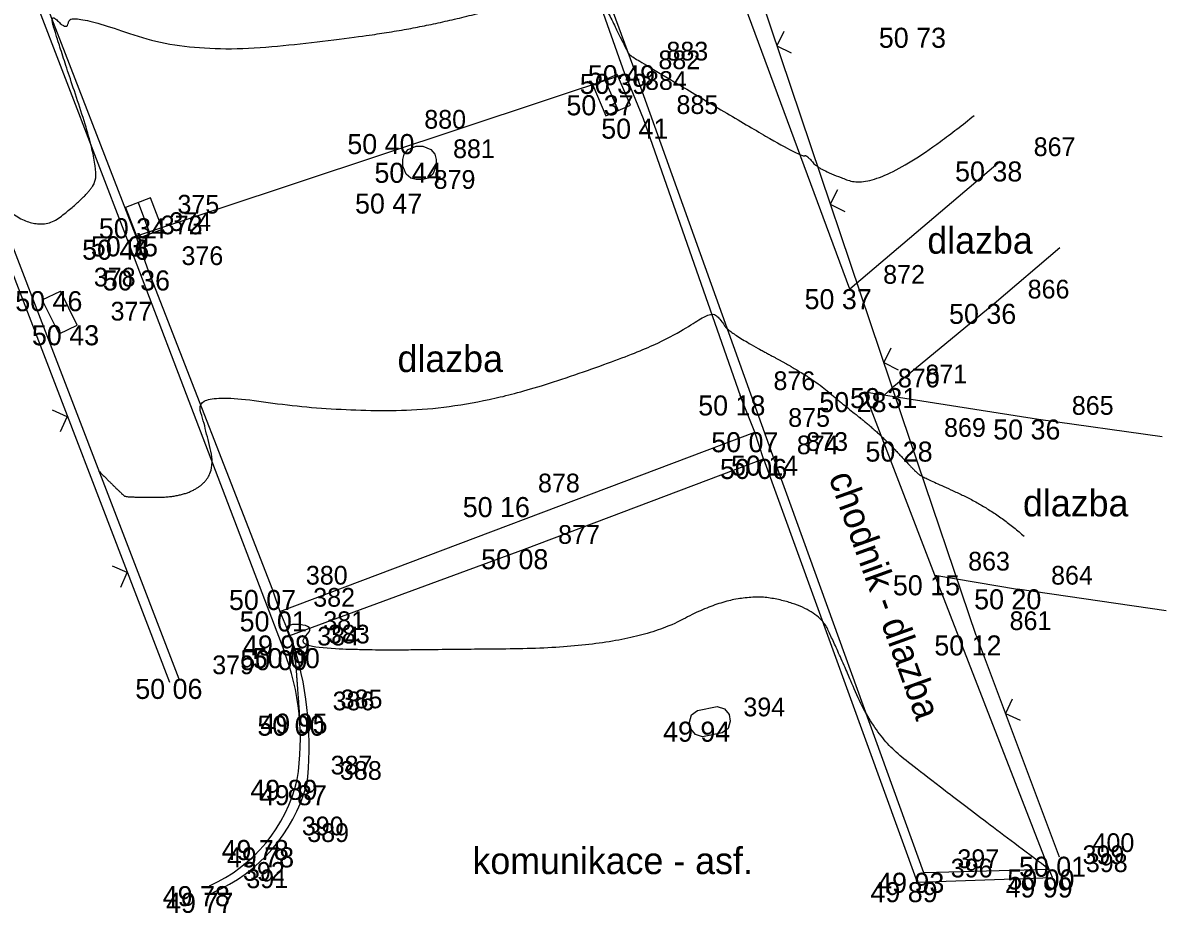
# Model space of a CAD drawing. Extents: x -704017 to -701500, y -1008977 to -1008450.
# Drawn here: x -703990.87 to -703973.78, y -1008677.56 to -1008664.25 of the extents above; entities that cross this region are included whole.
import ezdxf

# ---------------------------------------------------------------- set-up
doc = ezdxf.new("R2010")
doc.units = 0
for name, color, linetype in [('Z_body', 7, 'Continuous'), ('Z_body_cisla', 7, 'Continuous'), ('Z_body_vysky', 7, 'Continuous'), ('Z_chodnik', 7, 'Continuous'), ('Z_komunikace', 7, 'Continuous'), ('Z_obruby', 7, 'Continuous'), ('Z_popis', 7, 'Continuous'), ('Z_rozhrani_ploch', 7, 'Continuous'), ('Z_site_znaky_kanalizace', 7, 'Continuous'), ('Z_site_znaky_pilire', 7, 'Continuous'), ('Z_site_znaky_plynovod', 7, 'Continuous'), ('Z_teren_hrany_paty', 7, 'Continuous'), ('Z_vrstevnice_hlavni', 7, 'Continuous'), ('Z_vrstevnice_vedlejsi', 7, 'Continuous'), ('Z_vstupy', 7, 'Continuous')]:
    doc.layers.add(name, color=color, linetype=linetype)

# ---------------------------------------------------------------- blocks, each defined once
blk = doc.blocks.new('POINT_DISPLAY')
blk.add_line((0, 0), (0, 0))
blk = doc.blocks.new('Z212')
for p, q in [((-0.17, 0.17), (0, 0)), ((0, 0), (0.17, 0.17))]:
    blk.add_line(p, q)
blk = doc.blocks.new('Z620')
for p, q in [((-0.23, 0.13), (-0.17, 0.2)), ((-0.17, 0.2), (-0.05, 0.25)), ((-0.05, 0.25), (0.05, 0.25)), ((0.05, 0.25), (0.17, 0.2)), ((0.17, 0.2), (0.23, 0.13)), ((-0.25, 0.05), (-0.23, 0.13)), ((-0.25, -0.05), (-0.25, 0.05)), ((0.23, 0.13), (0.25, 0.05)), ((0.25, 0.05), (0.25, -0.05)), ((-0.2, -0.17), (-0.25, -0.05)), ((-0.13, -0.23), (-0.2, -0.17)), ((0.2, -0.17), (0.13, -0.23)), ((0.25, -0.05), (0.2, -0.17)), ((-0.05, -0.25), (-0.13, -0.23)), ((0.05, -0.25), (-0.05, -0.25)), ((0.13, -0.23), (0.05, -0.25))]:
    blk.add_line(p, q)
blk = doc.blocks.new('Z38')
for p, q in [((0.25, 0.2), (-0.25, 0.2)), ((-0.25, 0.2), (-0.25, -0.2)), ((0.25, -0.2), (0.25, 0.2)), ((-0.25, 0), (0.25, 0)), ((-0.25, -0.2), (0.25, -0.2))]:
    blk.add_line(p, q)
blk = doc.blocks.new('Z14')
for p, q in [((-0.25, 0.15), (-0.15, 0.2)), ((-0.15, 0.2), (0.15, 0.2)), ((0.15, 0.2), (0.25, 0.15)), ((-0.3, 0.05), (-0.25, 0.15)), ((-0.3, -0.05), (-0.3, 0.05)), ((0.25, 0.15), (0.3, 0.05)), ((0.3, 0.05), (0.3, -0.05)), ((-0.25, -0.15), (-0.3, -0.05)), ((-0.15, -0.2), (-0.25, -0.15)), ((0.25, -0.15), (0.15, -0.2)), ((0.3, -0.05), (0.25, -0.15)), ((0.15, -0.2), (-0.15, -0.2))]:
    blk.add_line(p, q)

msp = doc.modelspace()

# ---------------------------------------------------------------- linework, layer by layer
at = {"layer": 'Z_chodnik'}
for p, q in [((-703978.51, -1008668.23), (-703980.58, -1008662.63)), ((-703976.26, -1008666.32), (-703978.51, -1008668.23)), ((-703975.37, -1008667.61), (-703976.35, -1008668.45)), ((-703976.35, -1008668.45), (-703977.88, -1008669.71)), ((-703977.88, -1008669.71), (-703978, -1008669.82)), ((-703977.24, -1008672.51), (-703978.29, -1008669.77)), ((-703975.69, -1008670.18), (-703978.29, -1008669.77)), ((-703973.84, -1008670.44), (-703975.69, -1008670.18)), ((-703975.53, -1008676.91), (-703977.24, -1008672.51)), ((-703977.24, -1008672.51), (-703976, -1008672.72)), ((-703973.78, -1008673.04), (-703976, -1008672.72)), ((-703975.48, -1008677.03), (-703975.53, -1008676.91))]:
    msp.add_line(p, q, dxfattribs=at)
at = {"layer": 'Z_komunikace'}
for p, q in [((-703992.64, -1008658.49), (-703989.18, -1008667.44)), ((-703981.87, -1008665.01), (-703982.9, -1008662.09)), ((-703981.87, -1008665.01), (-703981.6, -1008665.68)), ((-703981.6, -1008665.68), (-703980.15, -1008669.82)), ((-703989.18, -1008667.44), (-703989, -1008667.95)), ((-703989, -1008667.95), (-703987.14, -1008672.73)), ((-703979.93, -1008670.37), (-703980.15, -1008669.82)), ((-703979.8, -1008670.77), (-703979.93, -1008670.37)), ((-703979.8, -1008670.77), (-703977.5, -1008677.1)), ((-703987.14, -1008672.73), (-703987.03, -1008673.05)), ((-703987.03, -1008673.05), (-703986.88, -1008673.41)), ((-703986.88, -1008673.41), (-703986.81, -1008673.6)), ((-703977.5, -1008677.1), (-703975.48, -1008677.03))]:
    msp.add_line(p, q, dxfattribs=at)
for centre, radius, start, end in [((-703991.75, -1008675.07), 5.158, 353.5102, 16.5257), ((-703989.02, -1008674.98), 2.483, 293.5439, 344.438)]:
    msp.add_arc(centre, radius, start, end, dxfattribs=at)
at = {"layer": 'Z_obruby'}
for p, q in [((-703992.74, -1008658.56), (-703989.31, -1008667.49)), ((-703981.75, -1008664.88), (-703982.8, -1008662.04)), ((-703979.66, -1008670.72), (-703981.75, -1008664.88)), ((-703989.31, -1008667.49), (-703986.97, -1008673.63)), ((-703977.4, -1008676.96), (-703979.66, -1008670.72)), ((-703975.53, -1008676.91), (-703977.4, -1008676.96))]:
    msp.add_line(p, q, dxfattribs=at)
for centre, radius, start, end in [((-703990.49, -1008674.97), 3.768, 350.8881, 20.8839), ((-703989.03, -1008675.04), 2.32, 294.152, 346.8779)]:
    msp.add_arc(centre, radius, start, end, dxfattribs=at)
at = {"layer": 'Z_rozhrani_ploch'}
for p, q in [((-703989.18, -1008667.44), (-703981.87, -1008665.01)), ((-703987.03, -1008673.05), (-703979.93, -1008670.37)), ((-703983.37, -1008672.12), (-703979.8, -1008670.77)), ((-703986.88, -1008673.41), (-703983.37, -1008672.12))]:
    msp.add_line(p, q, dxfattribs=at)
at = {"layer": 'Z_site_znaky_pilire'}
for p, q in [((-703990.58, -1008668.39), (-703990.31, -1008668.26)), ((-703990.06, -1008668.77), (-703990.31, -1008668.26)), ((-703990.33, -1008668.9), (-703990.58, -1008668.39)), ((-703990.33, -1008668.9), (-703990.06, -1008668.77))]:
    msp.add_line(p, q, dxfattribs=at)
at = {"layer": 'Z_teren_hrany_paty'}
for p, q in [((-703977.6, -1008670.51), (-703980.28, -1008662.56)), ((-703992.45, -1008664.3), (-703988.68, -1008674.11)), ((-703992.31, -1008664.25), (-703988.54, -1008674.06)), ((-703976.62, -1008673.41), (-703975.38, -1008676.72))]:
    msp.add_line(p, q, dxfattribs=at)
at = {"layer": 'Z_vrstevnice_hlavni'}
msp.add_open_spline([(-703975.53, -1008676.91), (-703977.349, -1008675.544), (-703978.153, -1008674.88), (-703978.692, -1008673.627), (-703978.988, -1008673.004), (-703980.2, -1008672.735), (-703981.787, -1008673.594), (-703985.333, -1008673.63), (-703985.37, -1008673.634), (-703986.81, -1008673.6), (-703986.49, -1008673.267), (-703986.955, -1008673.23), (-703986.889, -1008673.432), (-703986.81, -1008673.6), (-703986.737, -1008674.589), (-703986.74, -1008674.61), (-703986.743, -1008674.608)], degree=2, dxfattribs=at)
at = {"layer": 'Z_vrstevnice_vedlejsi'}
for points in [[(-703991.305, -1008666.866), (-703990.71, -1008667.458), (-703989.91, -1008666.842), (-703989.702, -1008666.469), (-703990.341, -1008664.544), (-703990.478, -1008664.084), (-703990.202, -1008664.369), (-703990.172, -1008664.089), (-703988.378, -1008664.725), (-703985.803, -1008664.468), (-703984.247, -1008664.174), (-703982.363, -1008663.613), (-703981.838, -1008664.665), (-703981.808, -1008664.722), (-703981.703, -1008664.79), (-703979.237, -1008666.262), (-703979.164, -1008666.207), (-703978.967, -1008666.455), (-703978.04, -1008666.762), (-703976.651, -1008665.634)], [(-703989.734, -1008670.954), (-703989.381, -1008671.305), (-703989.321, -1008671.344), (-703988.424, -1008671.343), (-703987.982, -1008670.975), (-703988.142, -1008670.312), (-703988.294, -1008669.763), (-703986.281, -1008670.062), (-703984.123, -1008670.022), (-703981.376, -1008669.091), (-703980.591, -1008668.56), (-703980.45, -1008668.667), (-703980.317, -1008668.885), (-703979.11, -1008669.529), (-703978.584, -1008669.974), (-703978.048, -1008670.402), (-703977.517, -1008670.972), (-703977.421, -1008671.04), (-703976.37, -1008671.516), (-703975.903, -1008671.926)]]:
    msp.add_open_spline(points, degree=2, dxfattribs=at)
at = {"layer": 'Z_vstupy'}
msp.add_line((-703976.62, -1008673.41), (-703977.6, -1008670.51), dxfattribs=at)

# ---------------------------------------------------------------- block references
at = {"layer": 'Z_body'}
for p in [(-703977.4, -1008664.32), (-703981.75, -1008664.88), (-703981.87, -1008665.01), (-703982.07, -1008665.33), (-703981.6, -1008665.68), (-703985.37, -1008665.91), (-703984.94, -1008666.34), (-703976.26, -1008666.32), (-703985.23, -1008666.8), (-703989.06, -1008667.17), (-703989.31, -1008667.49), (-703989.31, -1008667.49), (-703989.18, -1008667.44), (-703989, -1008667.95), (-703990.31, -1008668.26), (-703978.51, -1008668.23), (-703976.35, -1008668.45), (-703990.06, -1008668.77), (-703977.88, -1008669.71), (-703980.15, -1008669.82), (-703978.29, -1008669.77), (-703975.69, -1008670.18), (-703979.93, -1008670.37), (-703977.6, -1008670.51), (-703979.66, -1008670.72), (-703979.8, -1008670.77), (-703983.67, -1008671.34), (-703983.37, -1008672.12), (-703977.24, -1008672.51), (-703987.14, -1008672.73), (-703976, -1008672.72), (-703987.03, -1008673.05), (-703986.88, -1008673.41), (-703976.62, -1008673.41), (-703986.97, -1008673.63), (-703986.81, -1008673.6), (-703988.54, -1008674.06), (-703986.74, -1008674.61), (-703986.62, -1008674.58), (-703980.6, -1008674.7), (-703986.77, -1008675.57), (-703986.63, -1008675.65), (-703987.2, -1008676.47), (-703987.12, -1008676.58), (-703975.38, -1008676.72), (-703977.4, -1008676.96), (-703975.53, -1008676.91), (-703975.48, -1008677.03), (-703988.08, -1008677.16), (-703977.5, -1008677.1), (-703988.03, -1008677.26)]:
    msp.add_blockref('POINT_DISPLAY', p, dxfattribs=at)
at = {"layer": 'Z_site_znaky_kanalizace'}
for p, rotation in [((-703982.07, -1008665.33), -66.60000000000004), ((-703989.06, -1008667.17), -69.30000000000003)]:
    msp.add_blockref('Z38', p, dxfattribs=dict(at, rotation=rotation))
msp.add_blockref('Z620', (-703984.94, -1008666.34), dxfattribs=at)
at = {"layer": 'Z_site_znaky_plynovod', "rotation": 10.799999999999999}
msp.add_blockref('Z14', (-703980.6, -1008674.7), dxfattribs=at)
at = {"layer": 'Z_teren_hrany_paty'}
for p, rotation in [((-703979.6, -1008664.59), -71.4), ((-703978.8, -1008666.96), -71.4), ((-703978, -1008669.33), -71.4), ((-703990.21, -1008670.14), 111), ((-703989.31, -1008672.47), 111), ((-703976.18, -1008674.58), -69.50000000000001)]:
    msp.add_blockref('Z212', p, dxfattribs=dict(at, rotation=rotation))

# ---------------------------------------------------------------- texts
at = {"layer": 'Z_body_cisla'}
for s, p in [('883', (-703981.25, -1008664.81)), ('882', (-703981.37, -1008664.94)), ('884', (-703981.57, -1008665.25)), ('885', (-703981.1, -1008665.61)), ('880', (-703984.87, -1008665.83)), ('881', (-703984.44, -1008666.27)), ('867', (-703975.76, -1008666.24)), ('879', (-703984.73, -1008666.73)), ('375', (-703988.56, -1008667.1)), ('372', (-703988.81, -1008667.41)), ('373', (-703988.81, -1008667.41)), ('374', (-703988.68, -1008667.36)), ('376', (-703988.5, -1008667.87)), ('378', (-703989.81, -1008668.19)), ('872', (-703978.01, -1008668.15)), ('866', (-703975.85, -1008668.37)), ('377', (-703989.56, -1008668.7)), ('871', (-703977.38, -1008669.64)), ('876', (-703979.65, -1008669.74)), ('870', (-703977.79, -1008669.7)), ('865', (-703975.19, -1008670.11)), ('875', (-703979.43, -1008670.29)), ('869', (-703977.1, -1008670.44)), ('873', (-703979.16, -1008670.65)), ('874', (-703979.3, -1008670.7)), ('878', (-703983.17, -1008671.27)), ('877', (-703982.87, -1008672.04)), ('863', (-703976.74, -1008672.44)), ('380', (-703986.64, -1008672.65)), ('864', (-703975.5, -1008672.65)), ('382', (-703986.53, -1008672.98)), ('381', (-703986.38, -1008673.33)), ('861', (-703976.12, -1008673.33)), ('384', (-703986.47, -1008673.56)), ('383', (-703986.31, -1008673.53)), ('379', (-703988.04, -1008673.99)), ('386', (-703986.24, -1008674.53)), ('385', (-703986.12, -1008674.5)), ('394', (-703980.1, -1008674.62)), ('387', (-703986.27, -1008675.49)), ('388', (-703986.13, -1008675.57)), ('390', (-703986.7, -1008676.4)), ('389', (-703986.62, -1008676.5)), ('400', (-703974.88, -1008676.65)), ('399', (-703975.03, -1008676.83)), ('397', (-703976.9, -1008676.89)), ('398', (-703974.98, -1008676.95)), ('392', (-703987.58, -1008677.08)), ('396', (-703977, -1008677.03)), ('391', (-703987.53, -1008677.19))]:
    msp.add_text(s, height=0.28, dxfattribs=at).set_placement(p)
at = {"layer": 'Z_body_vysky'}
for s, p in [('50 73', (-703978.075, -1008664.62)), ('50 49', (-703982.425, -1008665.18)), ('50 39', (-703982.545, -1008665.31)), ('50 37', (-703982.745, -1008665.63)), ('50 41', (-703982.225, -1008665.98)), ('50 40', (-703986.02, -1008666.21)), ('50 44', (-703985.615, -1008666.64)), ('50 38', (-703976.935, -1008666.62)), ('50 47', (-703985.905, -1008667.1)), ('50 34', (-703989.735, -1008667.47)), ('50 46', (-703989.985, -1008667.79)), ('50 44', (-703989.985, -1008667.79)), ('50 35', (-703989.855, -1008667.74)), ('50 36', (-703989.675, -1008668.25)), ('50 46', (-703990.985, -1008668.56)), ('50 37', (-703979.185, -1008668.53)), ('50 36', (-703977.025, -1008668.75)), ('50 43', (-703990.735, -1008669.07)), ('50 31', (-703978.505, -1008670.01)), ('50 18', (-703980.775, -1008670.12)), ('50 28', (-703978.965, -1008670.07)), ('50 36', (-703976.365, -1008670.48)), ('50 07', (-703980.58, -1008670.67)), ('50 28', (-703978.275, -1008670.81)), ('50 14', (-703980.285, -1008671.02)), ('50 06', (-703980.45, -1008671.07)), ('50 16', (-703984.295, -1008671.64)), ('50 08', (-703984.02, -1008672.42)), ('50 15', (-703977.865, -1008672.81)), ('50 07', (-703987.79, -1008673.03)), ('50 20', (-703976.65, -1008673.02)), ('50 01', (-703987.63, -1008673.35)), ('49 99', (-703987.58, -1008673.71)), ('50 12', (-703977.245, -1008673.71)), ('50 09', (-703987.62, -1008673.93)), ('50 00', (-703987.435, -1008673.9)), ('50 06', (-703989.19, -1008674.36)), ('50 00', (-703987.365, -1008674.91)), ('49 95', (-703987.32, -1008674.88)), ('49 94', (-703981.3, -1008675)), ('49 89', (-703987.47, -1008675.87)), ('49 87', (-703987.33, -1008675.95)), ('49 78', (-703987.9, -1008676.77)), ('49 78', (-703987.82, -1008676.88)), ('50 01', (-703975.98, -1008677.02)), ('49 93', (-703978.1, -1008677.26)), ('49 99', (-703976.18, -1008677.33)), ('50 00', (-703976.155, -1008677.21)), ('49 78', (-703988.78, -1008677.46)), ('49 89', (-703978.2, -1008677.4)), ('49 77', (-703988.73, -1008677.56))]:
    msp.add_text(s, height=0.3, dxfattribs=at).set_placement(p)
at = {"layer": 'Z_popis'}
for s, p in [('dlazba', (-703977.35, -1008667.7)), ('dlazba', (-703985.27, -1008669.47)), ('dlazba', (-703975.92, -1008671.63)), ('komunikace - asf.', (-703984.15, -1008676.98))]:
    msp.add_text(s, height=0.4, dxfattribs=at).set_placement(p)
msp.add_text('chodnik - dlazba', height=0.4, rotation=289.8, dxfattribs=at).set_placement((-703978.83, -1008671.04))

doc.saveas('drawing.dxf')
